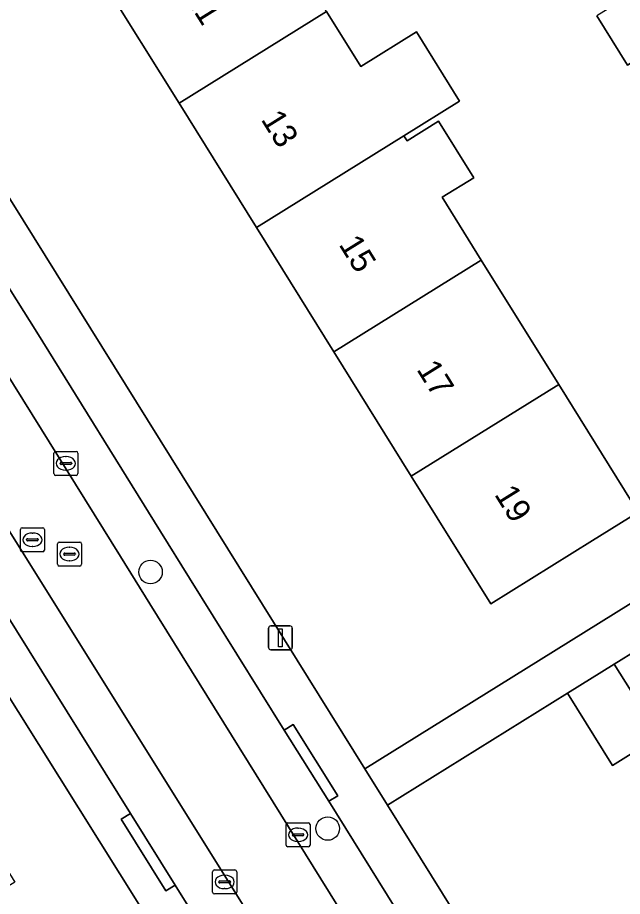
# Model space of a CAD drawing. Extents: x 159352 to 160617, y 385888 to 387323.
# Drawn here: x 159707.82 to 159733, y 386109.05 to 386145.65 of the extents above; entities that cross this region are included whole.
import ezdxf

# ---------------------------------------------------------------- set-up
doc = ezdxf.new("R2010")
doc.units = 0
for name, color, linetype in [('IMGEO_Boom', 7, 'Continuous'), ('IMGEO_Erf', 7, 'Continuous'), ('IMGEO_Kolk', 7, 'Continuous'), ('IMGEO_Lichtmast', 7, 'Continuous'), ('IMGEO_Pand', 7, 'Continuous'), ('IMGEO_Pand_nummerreeks', 7, 'Continuous'), ('IMGEO_Parkeervlak_open', 7, 'Continuous'), ('IMGEO_Rijbaan_lokaal_open', 7, 'Continuous'), ('IMGEO_Rioolput', 7, 'Continuous'), ('IMGEO_Voetpad_open', 7, 'Continuous')]:
    doc.layers.add(name, color=color, linetype=linetype)

msp = doc.modelspace()

# ---------------------------------------------------------------- linework, layer by layer
at = {"layer": 'IMGEO_Boom'}
for centre in [(159713.353, 386122.558), (159720.73, 386111.874)]:
    msp.add_circle(centre, 0.489, dxfattribs=at)
at = {"layer": 'IMGEO_Erf'}
for points in [[(159685.685, 386173.135), (159722.272, 386114.357), (159728.985, 386118.536), (159746.659, 386129.537), (159742.836, 386135.315), (159739.669, 386133.362), (159738.417, 386135.393), (159735.204, 386140.604), (159738.27, 386142.494), (159736.319, 386145.61), (159733.216, 386143.666), (159731.929, 386145.722)], [(159681.365, 386150.113), (159684.605, 386144.946), (159687.844, 386139.78), (159691.083, 386134.614), (159694.323, 386129.447), (159697.577, 386124.257), (159700.802, 386119.114), (159704.041, 386113.948), (159705.491, 386111.635), (159706.188, 386112.069), (159707.7, 386109.641), (159707.002, 386109.206), (159707.35, 386108.646), (159705.102, 386107.246), (159706.688, 386104.7), (159712.934, 386108.61), (159677.208, 386165.677)], [(159720.677, 386145.904), (159722.108, 386143.604), (159724.427, 386145.049), (159726.218, 386142.17), (159723.9, 386140.724), (159724.032, 386140.512), (159725.347, 386141.329), (159726.807, 386138.981), (159725.493, 386138.164), (159727.122, 386135.545), (159730.345, 386130.367), (159733.651, 386125.054), (159731.76, 386123.877), (159727.514, 386121.235), (159724.209, 386126.546), (159720.986, 386131.725), (159717.764, 386136.904), (159714.541, 386142.083), (159711.318, 386147.263)], [(159734.543, 386115.718), (159732.59, 386114.502), (159730.714, 386117.516), (159723.212, 386112.846), (159738.007, 386089.077)]]:
    msp.add_lwpolyline(points, dxfattribs=at)
at = {"layer": 'IMGEO_Kolk'}
for p, q in [((159709.329, 386126.657), (159709.329, 386127.509)), ((159709.404, 386127.583), (159710.256, 386127.583)), ((159710.33, 386127.509), (159710.33, 386126.657)), ((159709.631, 386127.126), (159710.029, 386127.126)), ((159709.817, 386127.363), (159709.842, 386127.363)), ((159709.588, 386127.077), (159709.588, 386127.089)), ((159710.026, 386127.04), (159709.628, 386127.04)), ((159709.84, 386126.803), (159709.815, 386126.803)), ((159710.072, 386127.089), (159710.072, 386127.077)), ((159710.256, 386126.583), (159709.404, 386126.583)), ((159718.996, 386111.188), (159718.996, 386112.04)), ((159719.071, 386112.114), (159719.923, 386112.114)), ((159719.484, 386111.894), (159719.509, 386111.894)), ((159719.997, 386112.04), (159719.997, 386111.188)), ((159719.255, 386111.608), (159719.255, 386111.62)), ((159719.693, 386111.571), (159719.295, 386111.571)), ((159719.298, 386111.657), (159719.696, 386111.657)), ((159719.739, 386111.62), (159719.739, 386111.608)), ((159719.923, 386111.114), (159719.071, 386111.114)), ((159719.507, 386111.334), (159719.482, 386111.334)), ((159715.939, 386109.226), (159715.939, 386110.078)), ((159716.014, 386110.152), (159716.866, 386110.152)), ((159716.427, 386109.932), (159716.452, 386109.932)), ((159716.94, 386110.078), (159716.94, 386109.226)), ((159716.198, 386109.646), (159716.198, 386109.658)), ((159716.636, 386109.609), (159716.238, 386109.609)), ((159716.241, 386109.695), (159716.639, 386109.695)), ((159716.682, 386109.658), (159716.682, 386109.646)), ((159716.45, 386109.372), (159716.425, 386109.372)), ((159716.866, 386109.152), (159716.014, 386109.152))]:
    msp.add_line(p, q, dxfattribs=at)
for points in [[(159709.329, 386126.657), (159709.329, 386127.509)], [(159709.404, 386127.583), (159710.256, 386127.583)], [(159710.33, 386127.509), (159710.33, 386126.657)], [(159710.256, 386126.583), (159709.404, 386126.583)], [(159718.996, 386111.188), (159718.996, 386112.04)], [(159719.071, 386112.114), (159719.923, 386112.114)], [(159719.997, 386112.04), (159719.997, 386111.188)], [(159719.923, 386111.114), (159719.071, 386111.114)], [(159715.939, 386109.226), (159715.939, 386110.078)], [(159716.014, 386110.152), (159716.866, 386110.152)], [(159716.94, 386110.078), (159716.94, 386109.226)], [(159716.866, 386109.152), (159716.014, 386109.152)]]:
    msp.add_lwpolyline(points, dxfattribs=at)
for centre, radius, start, end in [((159709.406, 386127.507), 0.0765, 91.552, 178.448), ((159709.406, 386127.507), 0.0765, 91.552, 178.448), ((159710.254, 386127.507), 0.0765, 1.552, 88.448), ((159710.254, 386127.507), 0.0765, 1.552, 88.448), ((159709.628, 386127.086), 0.0403, 85.8775, 175.7526), ((159710.033, 386127.088), 0.0386, 1.7309, 96.639), ((159709.625, 386127.076), 0.0366, 178.938, 274.7102), ((159710.029, 386127.083), 0.043, 264.8664, 352.4533), ((159709.406, 386126.659), 0.0765, 181.552, 268.448), ((159709.406, 386126.659), 0.0765, 181.552, 268.448), ((159710.254, 386126.659), 0.0765, 271.552, 358.448), ((159710.254, 386126.659), 0.0765, 271.552, 358.448), ((159719.073, 386112.038), 0.0765, 91.552, 178.448), ((159719.073, 386112.038), 0.0765, 91.552, 178.448), ((159719.921, 386112.038), 0.0765, 1.552, 88.448), ((159719.921, 386112.038), 0.0765, 1.552, 88.448), ((159719.295, 386111.617), 0.0403, 85.8775, 175.7526), ((159719.292, 386111.607), 0.0366, 178.938, 274.7102), ((159719.696, 386111.614), 0.043, 264.8664, 352.4533), ((159719.7, 386111.619), 0.0386, 1.7309, 96.639), ((159719.073, 386111.19), 0.0765, 181.552, 268.448), ((159719.073, 386111.19), 0.0765, 181.552, 268.448), ((159719.921, 386111.19), 0.0765, 271.552, 358.448), ((159719.921, 386111.19), 0.0765, 271.552, 358.448), ((159716.016, 386110.076), 0.0765, 91.552, 178.448), ((159716.016, 386110.076), 0.0765, 91.552, 178.448), ((159716.864, 386110.076), 0.0765, 1.552, 88.448), ((159716.864, 386110.076), 0.0765, 1.552, 88.448), ((159716.238, 386109.655), 0.0403, 85.8775, 175.7526), ((159716.235, 386109.645), 0.0366, 178.938, 274.7102), ((159716.639, 386109.652), 0.043, 264.8664, 352.4533), ((159716.643, 386109.657), 0.0386, 1.7309, 96.639), ((159716.016, 386109.228), 0.0765, 181.552, 268.448), ((159716.016, 386109.228), 0.0765, 181.552, 268.448), ((159716.864, 386109.228), 0.0765, 271.552, 358.448), ((159716.864, 386109.228), 0.0765, 271.552, 358.448)]:
    msp.add_arc(centre, radius, start, end, dxfattribs=at)
for centre, major_axis, ratio, start_param, end_param in [((159709.816, 386127.083), (-0.387, 0.002), 0.722429, 4.712389, 7.853982), ((159709.841, 386127.083), (-0.39, 0.002), 0.717154, 1.570796, 4.712389), ((159719.483, 386111.614), (-0.387, 0.002), 0.722429, 4.712389, 7.853982), ((159719.508, 386111.614), (-0.39, 0.002), 0.717154, 1.570796, 4.712389), ((159716.426, 386109.652), (-0.387, 0.002), 0.722429, 4.712389, 7.853982), ((159716.451, 386109.652), (-0.39, 0.002), 0.717154, 1.570796, 4.712389)]:
    msp.add_ellipse(centre, major_axis=major_axis, ratio=ratio, start_param=start_param, end_param=end_param, dxfattribs=at)
at = {"layer": 'IMGEO_Lichtmast'}
for p, q in [((159718.265, 386119.418), (159718.265, 386120.218)), ((159718.265, 386120.218), (159718.265, 386119.418)), ((159718.365, 386120.318), (159719.155, 386120.318)), ((159719.155, 386120.318), (159718.365, 386120.318)), ((159719.255, 386120.218), (159719.255, 386119.418)), ((159719.255, 386119.418), (159719.255, 386120.218)), ((159719.155, 386119.318), (159718.365, 386119.318)), ((159718.365, 386119.318), (159719.155, 386119.318))]:
    msp.add_line(p, q, dxfattribs=at)
msp.add_lwpolyline([(159718.685, 386120.193), (159718.835, 386120.193), (159718.835, 386119.443), (159718.685, 386119.443), (159718.685, 386120.193)], dxfattribs=at)
for centre, start, end in [((159718.365, 386120.218), 90, 180), ((159718.365, 386120.218), 90, 180), ((159719.155, 386120.218), 0, 90), ((159719.155, 386120.218), 360, 90), ((159718.365, 386119.418), 180, 270), ((159718.365, 386119.418), 180, 270), ((159719.155, 386119.418), 270, 0), ((159719.155, 386119.418), 270, 0)]:
    msp.add_arc(centre, 0.1, start, end, dxfattribs=at)
at = {"layer": 'IMGEO_Pand'}
for points in [[(159720.677, 386145.904), (159717.46, 386151.087), (159711.318, 386147.263), (159714.541, 386142.083)], [(159733.216, 386143.666), (159736.319, 386145.61), (159735.037, 386147.657), (159731.929, 386145.722)], [(159714.541, 386142.083), (159717.764, 386136.904), (159723.9, 386140.724), (159726.218, 386142.17), (159724.427, 386145.049), (159722.108, 386143.604), (159720.677, 386145.904)], [(159725.347, 386141.329), (159724.032, 386140.512), (159723.9, 386140.724), (159717.764, 386136.904), (159720.986, 386131.725), (159727.122, 386135.545), (159725.493, 386138.164), (159726.807, 386138.981)], [(159730.345, 386130.367), (159727.122, 386135.545), (159720.986, 386131.725), (159724.209, 386126.546)], [(159724.209, 386126.546), (159727.514, 386121.235), (159731.76, 386123.877), (159733.651, 386125.054), (159730.345, 386130.367)], [(159734.543, 386115.718), (159736.496, 386116.933), (159734.621, 386119.947), (159732.656, 386118.724)], [(159732.656, 386118.724), (159730.714, 386117.516), (159732.59, 386114.502), (159734.543, 386115.718)]]:
    msp.add_lwpolyline(points, close=True, dxfattribs=at)
at = {"layer": 'IMGEO_Parkeervlak_open'}
for points in [[(159729.424, 386089.133), (159684.734, 386160.648)], [(159708.615, 386132.541), (159707.231, 386134.755)], [(159713.768, 386124.242), (159708.615, 386132.541)], [(159706.934, 386131.508), (159712.101, 386123.199)], [(159714.974, 386122.307), (159713.768, 386124.242)], [(159705.653, 386123.513), (159712.525, 386112.5)], [(159712.101, 386123.199), (159713.32, 386121.238)], [(159718.917, 386115.978), (159714.974, 386122.307)], [(159713.32, 386121.238), (159732.063, 386091.102)], [(159720.775, 386113.01), (159718.917, 386115.978)], [(159732.147, 386094.729), (159720.775, 386113.01)], [(159712.525, 386112.5), (159714.373, 386109.524)], [(159714.373, 386109.524), (159715.436, 386107.819)]]:
    msp.add_lwpolyline(points, dxfattribs=at)
at = {"layer": 'IMGEO_Rijbaan_lokaal_open'}
msp.add_lwpolyline([(159706.934, 386131.508), (159705.576, 386133.684), (159700.717, 386141.456), (159699.735, 386143.025), (159695.462, 386149.864), (159694.078, 386152.113), (159686.42, 386164.358), (159685.102, 386166.476), (159682.211, 386164.651), (159684.734, 386160.648), (159729.424, 386089.133), (159732.198, 386090.885), (159732.063, 386091.102), (159713.32, 386121.238), (159712.101, 386123.199)], close=True, dxfattribs=at)
at = {"layer": 'IMGEO_Rioolput'}
for p, q in [((159707.937, 386123.475), (159707.937, 386124.327)), ((159708.012, 386124.401), (159708.864, 386124.401)), ((159708.938, 386124.327), (159708.938, 386123.475)), ((159708.196, 386123.895), (159708.196, 386123.907)), ((159708.634, 386123.858), (159708.236, 386123.858)), ((159708.239, 386123.944), (159708.637, 386123.944)), ((159708.425, 386124.181), (159708.45, 386124.181)), ((159708.68, 386123.907), (159708.68, 386123.895)), ((159708.448, 386123.621), (159708.423, 386123.621)), ((159709.48, 386122.881), (159709.48, 386123.733)), ((159709.555, 386123.807), (159710.407, 386123.807)), ((159709.968, 386123.587), (159709.993, 386123.587)), ((159710.481, 386123.733), (159710.481, 386122.881)), ((159708.864, 386123.401), (159708.012, 386123.401)), ((159709.739, 386123.301), (159709.739, 386123.313)), ((159710.177, 386123.264), (159709.779, 386123.264)), ((159709.782, 386123.35), (159710.18, 386123.35)), ((159710.223, 386123.313), (159710.223, 386123.301)), ((159710.407, 386122.807), (159709.555, 386122.807)), ((159709.991, 386123.027), (159709.966, 386123.027))]:
    msp.add_line(p, q, dxfattribs=at)
for points in [[(159707.937, 386123.475), (159707.937, 386124.327)], [(159708.012, 386124.401), (159708.864, 386124.401)], [(159708.938, 386124.327), (159708.938, 386123.475)], [(159709.48, 386122.881), (159709.48, 386123.733)], [(159709.555, 386123.807), (159710.407, 386123.807)], [(159710.481, 386123.733), (159710.481, 386122.881)], [(159708.864, 386123.401), (159708.012, 386123.401)], [(159710.407, 386122.807), (159709.555, 386122.807)]]:
    msp.add_lwpolyline(points, dxfattribs=at)
for centre, radius, start, end in [((159708.014, 386124.325), 0.0765, 91.552, 178.448), ((159708.014, 386124.325), 0.0765, 91.552, 178.448), ((159708.862, 386124.325), 0.0765, 1.552, 88.448), ((159708.862, 386124.325), 0.0765, 1.552, 88.448), ((159708.236, 386123.904), 0.0403, 85.8775, 175.7526), ((159708.233, 386123.894), 0.0366, 178.938, 274.7102), ((159708.637, 386123.901), 0.043, 264.8664, 352.4533), ((159708.641, 386123.906), 0.0386, 1.7309, 96.639), ((159708.014, 386123.477), 0.0765, 181.552, 268.448), ((159708.014, 386123.477), 0.0765, 181.552, 268.448), ((159708.862, 386123.477), 0.0765, 271.552, 358.448), ((159708.862, 386123.477), 0.0765, 271.552, 358.448), ((159709.557, 386123.731), 0.0765, 91.552, 178.448), ((159709.557, 386123.731), 0.0765, 91.552, 178.448), ((159710.405, 386123.731), 0.0765, 1.552, 88.448), ((159710.405, 386123.731), 0.0765, 1.552, 88.448), ((159709.779, 386123.31), 0.0403, 85.8775, 175.7526), ((159709.776, 386123.3), 0.0366, 178.938, 274.7102), ((159710.18, 386123.307), 0.043, 264.8664, 352.4533), ((159710.184, 386123.312), 0.0386, 1.7309, 96.639), ((159709.557, 386122.883), 0.0765, 181.552, 268.448), ((159709.557, 386122.883), 0.0765, 181.552, 268.448), ((159710.405, 386122.883), 0.0765, 271.552, 358.448), ((159710.405, 386122.883), 0.0765, 271.552, 358.448)]:
    msp.add_arc(centre, radius, start, end, dxfattribs=at)
for centre, major_axis, ratio, start_param, end_param in [((159708.424, 386123.901), (-0.387, 0.002), 0.722429, 4.712389, 7.853982), ((159708.449, 386123.901), (-0.39, 0.002), 0.717154, 1.570796, 4.712389), ((159709.967, 386123.307), (-0.387, 0.002), 0.722429, 4.712389, 7.853982), ((159709.992, 386123.307), (-0.39, 0.002), 0.717154, 1.570796, 4.712389)]:
    msp.add_ellipse(centre, major_axis=major_axis, ratio=ratio, start_param=start_param, end_param=end_param, dxfattribs=at)
at = {"layer": 'IMGEO_Voetpad_open'}
for points in [[(159734.961, 386087.237), (159738.007, 386089.077), (159723.212, 386112.846), (159722.272, 386114.357), (159685.685, 386173.135)], [(159678.601, 386168.796), (159674.448, 386166.054), (159677.208, 386165.677), (159712.934, 386108.61), (159713.923, 386107.031), (159717.083, 386101.983), (159727.834, 386084.857), (159727.06, 386082.254), (159731.503, 386085.122)], [(159689.763, 386162.72), (159695.716, 386153.19), (159697.136, 386150.917), (159701.414, 386144.069), (159702.412, 386142.47), (159707.231, 386134.755), (159708.615, 386132.541), (159713.768, 386124.242), (159714.974, 386122.307), (159718.917, 386115.978), (159719.286, 386116.213), (159721.153, 386113.232), (159720.775, 386113.01), (159732.147, 386094.729)], [(159746.659, 386129.537), (159728.985, 386118.536), (159722.272, 386114.357), (159723.212, 386112.846), (159730.714, 386117.516), (159732.656, 386118.724), (159734.621, 386119.947)], [(159721.845, 386097.555), (159718.081, 386103.547), (159717.719, 386103.317), (159715.061, 386107.575), (159715.436, 386107.819), (159714.373, 386109.524), (159713.989, 386109.286), (159712.133, 386112.264), (159712.525, 386112.5), (159705.653, 386123.513)]]:
    msp.add_lwpolyline(points, dxfattribs=at)
for points in [[(159720.775, 386113.01), (159721.153, 386113.232), (159719.286, 386116.213), (159718.917, 386115.978)], [(159714.373, 386109.524), (159712.525, 386112.5), (159712.133, 386112.264), (159713.989, 386109.286)]]:
    msp.add_lwpolyline(points, close=True, dxfattribs=at)

# ---------------------------------------------------------------- texts
at = {"layer": 'IMGEO_Pand_nummerreeks'}
for s, rotation, p in [('11', 301.8931, (159714.75, 386146.516)), ('13', 301.8931, (159717.928, 386141.408)), ('15', 301.8906, (159721.167, 386136.202)), ('17', 301.8931, (159724.406, 386130.999)), ('19', 301.8931, (159727.645, 386125.794))]:
    msp.add_text(s, height=1, rotation=rotation, dxfattribs=at).set_placement(p)

doc.saveas('drawing.dxf')
